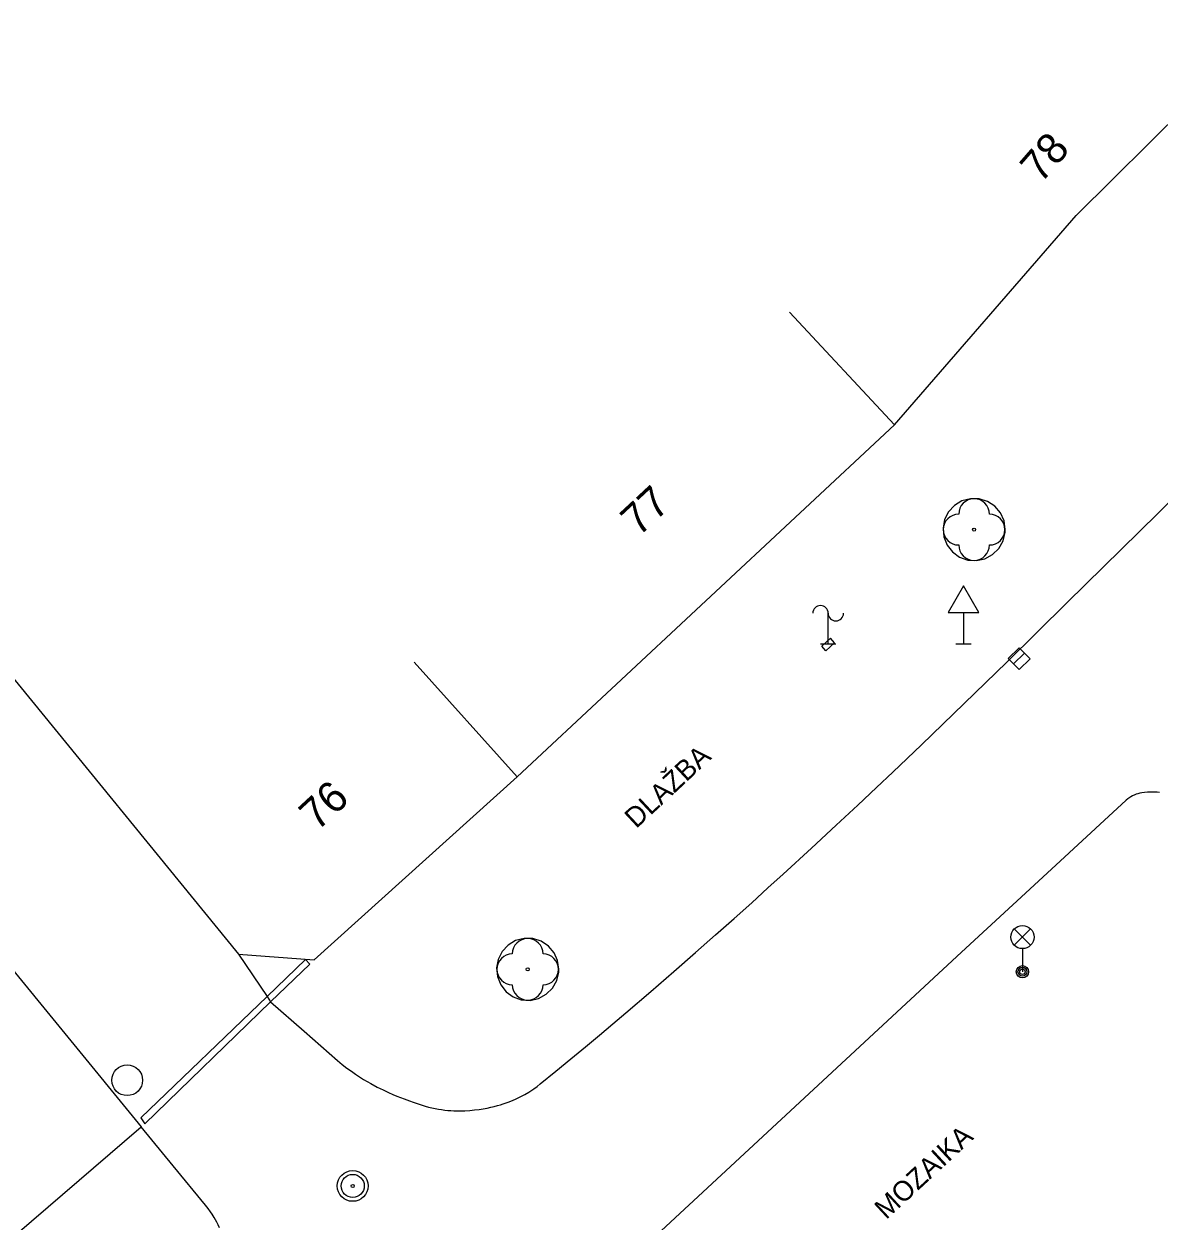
# Model space of a CAD drawing. Extents: x -538441 to -536770, y -1181008 to -1179809.
# Drawn here: x -537849.95 to -537813.11, y -1180900.11 to -1180861.26 of the extents above; entities that cross this region are included whole.
import ezdxf

# ---------------------------------------------------------------- set-up
doc = ezdxf.new("R2010")
doc.units = 0
for name, color, linetype in [('Vrstva 10', 7, 'Continuous'), ('Vrstva 11', 7, 'Continuous'), ('Vrstva 21', 7, 'Continuous'), ('Vrstva 22', 7, 'Continuous'), ('Vrstva 24', 7, 'Continuous'), ('Vrstva 27', 7, 'Continuous'), ('Vrstva 33', 7, 'Continuous'), ('Vrstva 34', 7, 'Continuous'), ('Vrstva 40', 7, 'Continuous'), ('Vrstva 47', 7, 'Continuous'), ('Vrstva 5', 7, 'Continuous')]:
    doc.layers.add(name, color=color, linetype=linetype)

msp = doc.modelspace()

# ---------------------------------------------------------------- linework, layer by layer
at = {"layer": 'Vrstva 10'}
for p, q in [((-537817.022, -1180889.082), (-537819.515, -1180891.385)), ((-537819.515, -1180891.385), (-537823.873, -1180895.418)), ((-537823.873, -1180895.418), (-537830.403, -1180901.472))]:
    msp.add_line(p, q, dxfattribs=at)
for points in [[(-537813.148, -1180877.146), (-537811.676, -1180875.701)], [(-537818.1, -1180877.67), (-537818.139, -1180877.389), (-537818.256, -1180877.131), (-537818.439, -1180876.914), (-537818.676, -1180876.758), (-537818.946, -1180876.673), (-537819.23, -1180876.667), (-537819.504, -1180876.74), (-537819.747, -1180876.886), (-537819.94, -1180877.094), (-537820.067, -1180877.347), (-537820.119, -1180877.626), (-537820.092, -1180877.908), (-537819.987, -1180878.172), (-537819.813, -1180878.396), (-537819.584, -1180878.562), (-537819.317, -1180878.659), (-537819.034, -1180878.678), (-537818.757, -1180878.617), (-537818.508, -1180878.481), (-537818.306, -1180878.282), (-537818.168, -1180878.035), (-537818.104, -1180877.758), (-537818.1, -1180877.67)], [(-537819.087, -1180882.983), (-537818.05, -1180881.97), (-537816.088, -1180880.041), (-537813.148, -1180877.146)], [(-537825.801, -1180889.301), (-537825.307, -1180888.853), (-537824.386, -1180888.009), (-537823.584, -1180887.267), (-537822.886, -1180886.615), (-537822.277, -1180886.043), (-537821.746, -1180885.54), (-537820.819, -1180884.656), (-537820.125, -1180883.989), (-537819.087, -1180882.983)], [(-537813.094, -1180886.201), (-537813.169, -1180886.194), (-537813.239, -1180886.189), (-537813.37, -1180886.187), (-537813.483, -1180886.191), (-537813.58, -1180886.2), (-537813.664, -1180886.213), (-537813.735, -1180886.228), (-537813.795, -1180886.244), (-537813.847, -1180886.261), (-537813.892, -1180886.277), (-537813.967, -1180886.311), (-537814.021, -1180886.34), (-537814.06, -1180886.364), (-537814.117, -1180886.405), (-537814.17, -1180886.45), (-537817.022, -1180889.082)], [(-537833.291, -1180895.739), (-537833.19, -1180895.66), (-537832.683, -1180895.245), (-537832.196, -1180894.843), (-537831.726, -1180894.453), (-537831.273, -1180894.075), (-537830.837, -1180893.708), (-537830.417, -1180893.352), (-537829.608, -1180892.661), (-537828.855, -1180892.011), (-537828.156, -1180891.4), (-537827.504, -1180890.826), (-537826.896, -1180890.286), (-537826.329, -1180889.778), (-537825.801, -1180889.301)], [(-537832.59, -1180891.94), (-537832.629, -1180891.659), (-537832.746, -1180891.401), (-537832.929, -1180891.184), (-537833.166, -1180891.028), (-537833.436, -1180890.943), (-537833.72, -1180890.937), (-537833.994, -1180891.01), (-537834.237, -1180891.156), (-537834.43, -1180891.364), (-537834.557, -1180891.617), (-537834.609, -1180891.896), (-537834.582, -1180892.178), (-537834.477, -1180892.442), (-537834.303, -1180892.666), (-537834.074, -1180892.832), (-537833.807, -1180892.929), (-537833.524, -1180892.948), (-537833.247, -1180892.887), (-537832.998, -1180892.751), (-537832.796, -1180892.552), (-537832.658, -1180892.305), (-537832.594, -1180892.028), (-537832.59, -1180891.94)], [(-537842.99, -1180891.45), (-537842.062, -1180892.825), (-537841.949, -1180892.992), (-537840.86, -1180893.946), (-537839.77, -1180894.9), (-537839.617, -1180895.029), (-537839.468, -1180895.146), (-537839.324, -1180895.251), (-537839.187, -1180895.346), (-537839.055, -1180895.433), (-537838.93, -1180895.511), (-537838.81, -1180895.582), (-537838.697, -1180895.646), (-537838.482, -1180895.761), (-537838.291, -1180895.857), (-537838.122, -1180895.936), (-537837.974, -1180896.002), (-537837.843, -1180896.057), (-537837.614, -1180896.148), (-537837.442, -1180896.212), (-537837.314, -1180896.257), (-537837.121, -1180896.321), (-537836.93, -1180896.38), (-537836.819, -1180896.411), (-537836.71, -1180896.437), (-537836.602, -1180896.46), (-537836.497, -1180896.479), (-537836.393, -1180896.495), (-537836.291, -1180896.507), (-537836.192, -1180896.517), (-537836.095, -1180896.525), (-537836, -1180896.53), (-537835.815, -1180896.533), (-537835.641, -1180896.53), (-537835.476, -1180896.52), (-537835.322, -1180896.506), (-537835.177, -1180896.488), (-537835.041, -1180896.467)], [(-537835.041, -1180896.467), (-537834.915, -1180896.443), (-537834.797, -1180896.417), (-537834.686, -1180896.391), (-537834.584, -1180896.363), (-537834.488, -1180896.335), (-537834.399, -1180896.307), (-537834.235, -1180896.249), (-537834.093, -1180896.193), (-537833.971, -1180896.14), (-537833.866, -1180896.09), (-537833.776, -1180896.044), (-537833.698, -1180896.002), (-537833.565, -1180895.925), (-537833.467, -1180895.863), (-537833.396, -1180895.815), (-537833.291, -1180895.739)], [(-537843.603, -1180900.329), (-537843.651, -1180900.229), (-537843.695, -1180900.144), (-537843.776, -1180899.998), (-537843.841, -1180899.891), (-537843.893, -1180899.813), (-537843.974, -1180899.7), (-537844.06, -1180899.59), (-537845.105, -1180898.32), (-537846.15, -1180897.05)]]:
    msp.add_lwpolyline(points, dxfattribs=at)
at = {"layer": 'Vrstva 11'}
for p, q in [((-537840.809, -1180891.621), (-537840.668, -1180891.769)), ((-537846.156, -1180896.758), (-537846.03, -1180896.95))]:
    msp.add_line(p, q, dxfattribs=at)
for points in [[(-537842.062, -1180892.825), (-537840.809, -1180891.621)], [(-537841.949, -1180892.992), (-537840.668, -1180891.769)], [(-537846.156, -1180896.758), (-537842.062, -1180892.825)], [(-537846.03, -1180896.95), (-537841.949, -1180892.992)]]:
    msp.add_lwpolyline(points, dxfattribs=at)
at = {"layer": 'Vrstva 21'}
for radius in [0.375, 0.05]:
    msp.add_circle((-537839.28, -1180898.97), radius, dxfattribs=at)
at = {"layer": 'Vrstva 22'}
for centre in [(-537819.11, -1180877.67), (-537833.6, -1180891.94)]:
    msp.add_circle(centre, 0.05, dxfattribs=at)
for centre, start, end in [((-537819.11, -1180877.17), 0, 180), ((-537819.61, -1180877.67), 90, 270), ((-537818.61, -1180877.67), 270, 90), ((-537819.11, -1180878.17), 180, 0), ((-537833.6, -1180891.44), 0, 180), ((-537834.1, -1180891.94), 90, 270), ((-537833.1, -1180891.94), 270, 90), ((-537833.6, -1180892.44), 180, 0)]:
    msp.add_arc(centre, 0.5, start, end, dxfattribs=at)
at = {"layer": 'Vrstva 24'}
for p, q in [((-537823.847, -1180881.384), (-537823.847, -1180880.384)), ((-537824.056, -1180881.453), (-537823.776, -1180881.193)), ((-537823.64, -1180881.34), (-537823.776, -1180881.193)), ((-537823.597, -1180881.384), (-537824.097, -1180881.384)), ((-537823.92, -1180881.6), (-537824.056, -1180881.453)), ((-537823.92, -1180881.6), (-537823.64, -1180881.34))]:
    msp.add_line(p, q, dxfattribs=at)
for centre, start, end in [((-537824.097, -1180880.384), 0, 180), ((-537823.597, -1180880.384), 180, 0)]:
    msp.add_arc(centre, 0.25, start, end, dxfattribs=at)
at = {"layer": 'Vrstva 27'}
msp.add_line((-537817.826, -1180882.031), (-537817.47, -1180881.681), dxfattribs=at)
msp.add_lwpolyline([(-537817.651, -1180882.21), (-537817.294, -1180881.859), (-537817.645, -1180881.502), (-537818.002, -1180881.853)], close=True, dxfattribs=at)
for centre in [(-537846.6, -1180895.54), (-537839.28, -1180898.97)]:
    msp.add_circle(centre, 0.5, dxfattribs=at)
at = {"layer": 'Vrstva 33'}
for p, q in [((-537817.805, -1180891.16), (-537817.275, -1180890.63)), ((-537817.805, -1180890.63), (-537817.275, -1180891.16)), ((-537817.54, -1180891.27), (-537817.54, -1180892.02))]:
    msp.add_line(p, q, dxfattribs=at)
for centre, radius in [((-537817.54, -1180890.895), 0.375), ((-537817.54, -1180892.02), 0.2), ((-537817.54, -1180892.02), 0.145), ((-537817.54, -1180892.02), 0.0876)]:
    msp.add_circle(centre, radius, dxfattribs=at)
at = {"layer": 'Vrstva 34'}
for p, q in [((-537819.451, -1180880.363), (-537819.451, -1180881.381)), ((-537819.701, -1180881.381), (-537819.201, -1180881.381))]:
    msp.add_line(p, q, dxfattribs=at)
msp.add_lwpolyline([(-537819.951, -1180880.363), (-537818.951, -1180880.363), (-537819.451, -1180879.497)], close=True, dxfattribs=at)
at = {"layer": 'Vrstva 5'}
for p, q in [((-537815.8, -1180867.48), (-537809.54, -1180861.26)), ((-537821.69, -1180874.27), (-537815.8, -1180867.48)), ((-537825.099, -1180870.613), (-537821.69, -1180874.27)), ((-537833.94, -1180885.69), (-537821.69, -1180874.27)), ((-537852.93, -1180879.28), (-537842.99, -1180891.45)), ((-537859.19, -1180881.13), (-537846.15, -1180897.05)), ((-537837.288, -1180881.976), (-537833.94, -1180885.69)), ((-537840.53, -1180891.63), (-537833.94, -1180885.69)), ((-537842.99, -1180891.45), (-537840.53, -1180891.63)), ((-537852.55, -1180902.55), (-537846.15, -1180897.05))]:
    msp.add_line(p, q, dxfattribs=at)

# ---------------------------------------------------------------- texts
at = {"layer": 'Vrstva 40'}
for s, rotation, p in [('DLAŽBA', 42.9917, (-537830.079, -1180887.392)), ('MOZAIKA', 42.8112, (-537821.965, -1180900.084))]:
    msp.add_text(s, height=0.65, rotation=rotation, dxfattribs=at).set_placement(p)
at = {"layer": 'Vrstva 47'}
for s, rotation, p in [('78', 48.9171, (-537816.942, -1180866.463)), ('77', 42.9126, (-537829.999, -1180877.919)), ('76', 42.7903, (-537840.433, -1180887.478))]:
    msp.add_text(s, height=1, rotation=rotation, dxfattribs=at).set_placement(p)

doc.saveas('drawing.dxf')
